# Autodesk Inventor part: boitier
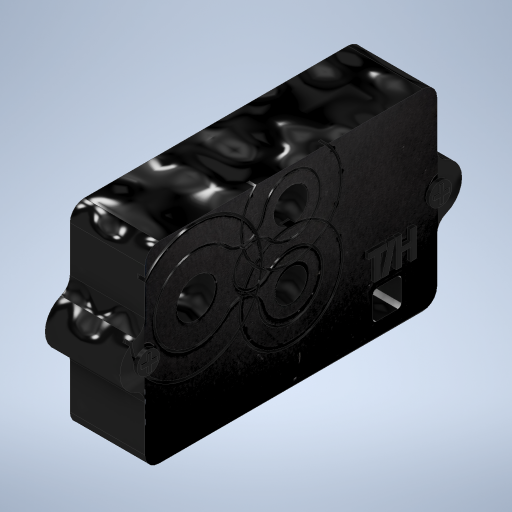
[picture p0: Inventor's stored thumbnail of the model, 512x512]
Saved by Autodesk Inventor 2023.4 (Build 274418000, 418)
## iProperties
Created: 2025-02
Part Number: boitier
Material: Générique
Document SubType Name: Modeling
Designer: bruno
Density: 1 g/cm^3
Appearance: Par défaut
Author: bruno
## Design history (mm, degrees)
sketch "Esquisse1"
  geometry: L1 (27, -2)-(27, -39); L2 (0, -39)-(0, -2); L3 (2, 0)-(8.377, 0); L4 (18.623, 0)-(25, 0); L5 (25, -41)-(18.623, -41); L6 (8.377, -41)-(2, -41); C1 r 1.579 at (13.5, 0); C2 r 1.579 at (13.5, -41); A1 r 2 centre (25, -2) between (27, -2) and (25, 0); A2 r 2 centre (2, -2) between (2, 0) and (0, -2); A3 r 2 centre (2, -39) between (0, -39) and (2, -41); A4 r 2 centre (25, -39) between (25, -41) and (27, -39); A5 r 3.5 centre (13.5, 0) between (16.76, 1.273) and (10.24, 1.273); A6 r 3.5 centre (13.5, -41) between (10.24, -42.273) and (16.76, -42.273); A7 r 2 centre (18.623, 2) between (16.76, 1.273) and (18.623, 0); A8 r 2 centre (8.377, 2) between (8.377, 0) and (10.24, 1.273); A9 r 2 centre (18.623, -43) between (18.623, -41) and (16.76, -42.273); A10 r 2 centre (8.377, -43) between (10.24, -42.273) and (8.377, -41); 8 further points
  constraints: 24 point on circle, 20 tangent, 12 centre point, 12 end point, 8 point on line, 6 equal radius, 5 parallel, 2 coincident, 2 horizontal, 2 perpendicular
  dimensions: "d0" = 27 distance of point (27, -41) point (0, -41); "d1" = 41 distance of point (27, 0) point (27, -41); "d2" = 2 radius of A1; "d3" = 7 diameter of A5; "d4" = 7 diameter of A6; "d5" = 2 radius of A7 (derived)
extrude "Extrusion1" new body sketch "Esquisse1" distance "d6" = 10.5; taper "d7" = 0 deg
sketch "Esquisse2"
  geometry: L1 (0, 0)-(-0.091, 27.352); L2 (-0.091, 27.352)-(41.073, 27.488); L3 (41.073, 27.488)-(41.164, 0.136); L4 (41.164, 0.136)-(0, 0); 1 further point; 1 other entity
  constraints: 1 coincident, 2 other
feature "Décalcomanie1" sketch "Esquisse2"
sketch "Esquisse3"
  geometry: L1 (36, 6)-(32, 6); L2 (32, 6)-(32, 2); L3 (32, 2)-(36, 2); L4 (36, 2)-(36, 6); L5 (2, 0)-(39, 0) reference; L6 (41, 2)-(41, 8.377) reference; C1 r 2.719 at (7.191, 17.514); C2 r 2.413 at (20.493, 22.086); C3 r 2.21 at (20.493, 12.387); 3 further points
  constraints: 8 end point, 3 centre point, 2 midpoint, 2 parallel, 1 horizontal, 1 perpendicular
  dimensions: "d33" = 2 distance from line of point (34, 2) L5; "d34" = 9 distance from line of point (32, 4) L6; "d35" = 4 distance of L1.start L1.end; "d36" = 4 distance of L3.end L1.start
extrude "Extrusion2" cut sketch "Esquisse3" distance "d37" = 5; taper "d38" = 0 deg
fillet "Congé1" dims "d39" = 0.5
sketch "Esquisse4"
  geometry: L1 (39, 27)-(2, 27) reference; L2 (0, 25)-(0, 18.623) reference; C1 r 2.413 at (20.493, 22.086) reference; C2 r 2.719 at (7.191, 17.514) reference; C3 r 2.21 at (20.493, 12.387) reference; C4 r 2.21 at (20.493, 12.387) reference; C5 r 7.086 at (20.493, 12.387); C6 r 7.374 at (20.493, 12.387); A1 r 3.949 centre (20.493, 22.086) between (17.525, 19.482) and (16.624, 22.876); A2 r 4.242 centre (20.493, 22.086) between (17.304, 19.288) and (16.323, 22.864); A3 r 2.953 centre (15.305, 17.534) between (17.525, 19.482) and (17.518, 15.579); A4 r 2.659 centre (15.305, 17.534) between (17.304, 19.288) and (17.207, 15.676); A5 r 6.876 centre (20.493, 22.086) between (15.684, 27) and (25.302, 27); A6 r 7.155 centre (20.493, 22.086) between (15.293, 27) and (25.693, 27); A7 r 4.355 centre (20.493, 12.387) between (16.147, 12.099) and (17.401, 15.454); A8 r 2.74 centre (13.638, 23.412) between (11.642, 21.535) and (15.668, 21.571); A9 r 3.034 centre (13.638, 23.412) between (11.4, 21.364) and (16.624, 22.876); A10 r 2.74 centre (13.638, 23.412) between (11.642, 21.535) and (16.323, 22.864); A11 r 5.705 centre (7.191, 17.514) between (11.4, 21.364) and (11.506, 13.783); A12 r 3.5 centre (0, 13.5) between (-1.273, 16.76) and (-1.273, 10.24) reference; A13 r 1.579 centre (0, 13.5) between (-1.284, 14.419) and (0.109, 11.925) reference; A14 r 9.022 centre (7.191, 17.514) between (-1.776, 16.516) and (-1.284, 14.419); A15 r 9.022 centre (7.191, 17.514) between (0.109, 11.925) and (0, 22.962); A16 r 9.399 centre (7.191, 17.514) between (-2.126, 16.28) and (-1.51, 13.96); A17 r 9.399 centre (7.191, 17.514) between (-0.401, 11.973) and (0, 23.565); A18 r 4.649 centre (20.493, 12.387) between (15.87, 11.893) and (17.207, 15.676); A19 r 5.998 centre (7.191, 17.514) between (11.642, 21.535) and (11.904, 13.803); A20 r 2.642 centre (13.505, 12.054) between (16.147, 12.099) and (11.506, 13.783); A21 r 2.371 centre (13.505, 12.054) between (15.87, 11.893) and (11.544, 13.386); 74 further points
  constraints: 49 point on circle, 21 centre point, 15 coincident, 6 point on line, 4 tangent
extrude "Extrusion3" cut sketch "Esquisse4" distance "d60" = 1; taper "d61" = 0 deg
sketch "Esquisse5"
  geometry: L1 (33.441, 11.273)-(30.948, 11.273); L2 (30.948, 11.273)-(30.948, 10.514); L3 (30.948, 10.514)-(33.441, 10.514); L4 (33.441, 10.514)-(33.441, 11.273); L5 (31.742, 10.514)-(32.569, 10.514); L6 (32.569, 10.514)-(32.569, 7.352); L7 (32.569, 7.352)-(31.742, 7.352); L8 (31.742, 7.352)-(31.742, 10.514); L9 (34.812, 11.273)-(35.583, 11.273); L10 (35.583, 11.273)-(35.583, 7.352); L11 (35.583, 7.352)-(34.812, 7.352); L12 (34.812, 7.352)-(34.812, 11.273); L13 (36.807, 11.273)-(37.611, 11.273); L14 (37.611, 11.273)-(37.611, 7.352); L15 (37.611, 7.352)-(36.807, 7.352); L16 (36.807, 7.352)-(36.807, 11.273); L17 (35.583, 9.755)-(36.807, 9.755); L18 (36.807, 9.755)-(36.807, 9.109); L19 (36.807, 9.109)-(35.583, 9.109); L20 (35.583, 9.109)-(35.583, 9.755); L21 (34.688, 11.273)-(33.759, 11.273); L22 (33.759, 11.273)-(32.75, 7.352); L23 (32.75, 7.352)-(33.679, 7.352); L24 (33.679, 7.352)-(34.688, 11.273); 4 further points
  constraints: 48 end point, 12 parallel, 7 point on line, 6 horizontal, 5 perpendicular
extrude "Extrusion4" join sketch "Esquisse5" distance "d62" = 0.5; taper "d63" = 0 deg
sketch "Esquisse6"
  geometry: C1 r 1.579 at (41, 13.5) reference; C2 r 1.579 at (0, 13.5); A1 r 1.579 centre (0, 13.5) between (0.109, 11.925) and (-1.284, 14.419) reference; 3 further points
  constraints: 1 centre point, 1 coincident, 1 concentric
extrude "Extrusion5" join sketch "Esquisse6" distance "d64" = 0.5; taper "d65" = 0 deg
sketch "Esquisse7"
  geometry: L1 (-0.217, 1.22)-(0.26, 1.22); L2 (0.26, 1.22)-(0.26, -1.125); L3 (0.26, -1.125)-(-0.217, -1.125); L4 (-0.217, -1.125)-(-0.217, 1.22); L5 (-1.101, 0.293)-(1.089, 0.293); L6 (1.089, 0.293)-(1.089, -0.226); L7 (1.089, -0.226)-(-1.101, -0.226); L8 (-1.101, -0.226)-(-1.101, 0.293); 5 further points
  constraints: 16 end point, 4 parallel, 2 horizontal, 2 perpendicular
extrude "Extrusion6" join sketch "Esquisse7" distance "d66" = 0.2; taper "d67" = 0 deg
pattern_linear "Réseau rectangulaire1" dims "d70" = 41
node "Solide1"
node "Image1"
node "Boucle projetée1"
